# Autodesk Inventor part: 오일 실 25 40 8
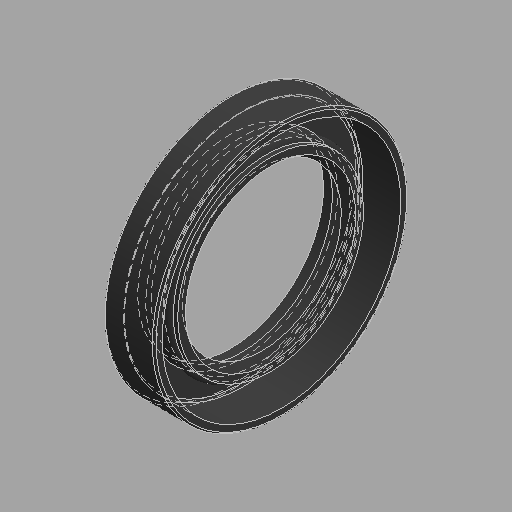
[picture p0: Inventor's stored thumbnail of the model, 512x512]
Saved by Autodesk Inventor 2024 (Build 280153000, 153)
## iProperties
Created: 2025-11
Part Number: 오일 실 25 40 8
Material: 고무
Description: 오일-실
Document SubType Name: Modeling
Designer: Edu09
Density: 0.93 g/cm^3
Appearance: 기본값
Author: jhkim
Sending System: Autodesk Inventor 2026
Preprocessor: ST-DEVELOPER v20.1
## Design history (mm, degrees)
feature "Solid1"
node "솔리드1"
